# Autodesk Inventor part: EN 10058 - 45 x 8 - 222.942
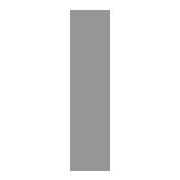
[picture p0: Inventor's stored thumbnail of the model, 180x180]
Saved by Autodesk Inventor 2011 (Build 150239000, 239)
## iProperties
IsCustomPart: 1
Created: 2010-02
Part Number: EN 10058 - 45 x 8 - 222.942
Material: Steel, Mild
Description: flat steel bar 45*8
Document SubType Name: Modeling
Standard: DIN
Designer: PC
Standard Revision: 2004
Standards Organization: DIN
Language: en-US
Size Designation: 45 x 8
Categories: <MemberInstance><Categories><Category DisplayName="Structural Shapes" InternalName="089c4875-fa83-4c05-b084-43b9cc11f5ed" Mnemonic="GRDR"><CategoryParameter Dis
Stock Number: 45 x 8
Density: 7.86 g/cm^3
_CCFamilyMember: 49
_CCFamilyDisplayName: DIN EN 10058 - Hot rolled flat steel bars for general purposes
_FrameMemberDoc: Frame Member File
_Version: 15.0.0
_GetPNFromCC: 1
G_L: 222.942 mm
G_W: 8.000 mm
G_H: 45.000 mm
+3B209ABD-99B2-41CF-BF4E-0AED748AA8EE+CUTDETAIL1: Cut
Author: PC
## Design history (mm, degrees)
node "Start plane"
node "End plane"
sketch "Sketch"
  geometry: L1 (4, -22.5)-(-4, -22.5); L2 (-4, -22.5)-(-4, 22.5); L3 (-4, 22.5)-(4, 22.5); L4 (4, 22.5)-(4, -22.5); L5 (-6, 0)-(8, 0); L6 (0, -30)-(0, 40); L7 (0, 54)-(0, -44) reference; L8 (-9.2, 0)-(13.2, 0) reference
  constraints: 12 end point, 2 collinear, 2 parallel, 1 horizontal, 1 perpendicular
  dimensions: "d0" = 45 distance between parallel lines of L3 L1 (= G_W); "d1" = 8 distance between parallel lines of L4 L2 (= G_H); "d4" = 4 distance between parallel lines of L6 L4 (= 0.5 x d1); "d5" = 22.5 distance between parallel lines of L5 L3 (= 0.5 x d0)
extrude "Body" new body sketch "Sketch" stored distance "d2" = 222.94229 (= G_L); taper "d3" = 0 deg
node "Driven Length"
  sketch "Sketch3"
    geometry: L1 (0, 0)-(10, 0) reference
    constraints: 2 end point, 1 horizontal
  workplane "Work Plane3"
  sketch "Sketch4"
    geometry: L1 (-2, 0)-(12, 0) reference; L2 (-2, 222.942)-(12, 222.942) reference
    dimensions: "d9" = 222.94229 distance between parallel lines of L1 L2 (derived)
workplane "Work Plane4"
split "Split1"
body "Solid1"
other parameters: "G_W" = 45 [user parameter; used in 1 equation term], "G_H" = 8 [user parameter; used in 1 equation term], "G_L" = 222.94229 (= d9) [user parameter; used in 1 equation term], "G_OFFSET_START" = 0 [user parameter; used in 1 equation term], "G_OFFSET_END" = 77.94229 [user parameter; used in 1 equation term], "d6" = 0 (computed from G_OFFSET_START), "d7" = 222.94229 (= G_OFFSET_END + B_L), "B_L" = 145 [user parameter; used in 1 equation term], "d8" = 90 deg, "MAS" = 0.283 [user parameter]
